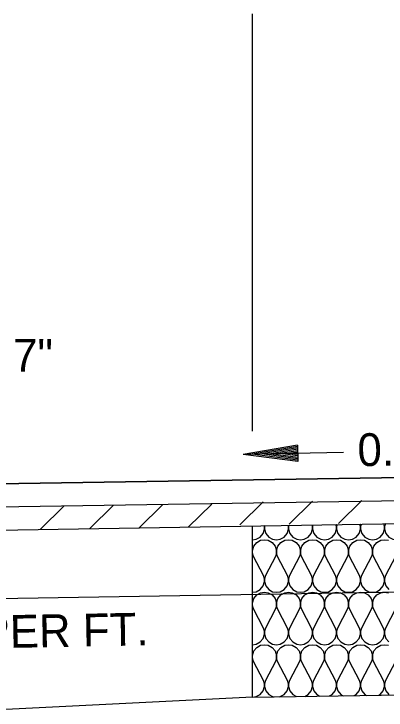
# Model space of a CAD drawing. Extents: x 635488 to 635865, y 290537 to 290973.
# Drawn here: x 635687.68 to 635694.5, y 290665.33 to 290678.07 of the extents above; entities that cross this region are included whole.
import ezdxf

# ---------------------------------------------------------------- set-up
doc = ezdxf.new("R2010")
doc.units = 0
for name, color, linetype in [('Default', 7, 'Continuous'), ('E_Existing ROW', 7, 'Continuous'), ('Level 13', 7, 'Continuous'), ('Level 3', 7, 'Continuous'), ('Level 43', 7, 'Continuous'), ('R_Dimension', 7, 'Continuous')]:
    doc.layers.add(name, color=color, linetype=linetype)

msp = doc.modelspace()

# ---------------------------------------------------------------- linework, layer by layer
at = {"layer": 'Default'}
for points in [[(635692.051, 290665.568), (635705.801, 290665.784), (635719.551, 290665.568)], [(635692.051, 290665.568), (635686.062, 290665.27)]]:
    msp.add_lwpolyline(points, dxfattribs=at)
at = {"layer": 'E_Existing ROW'}
for points in [[(635692.051, 290668.448), (635692.121, 290668.458), (635692.191, 290668.498), (635692.246, 290668.563), (635692.271, 290668.643), (635692.271, 290668.693), (635692.267, 290668.706)], [(635692.275, 290668.706), (635692.271, 290668.693), (635692.271, 290668.643), (635692.296, 290668.563), (635692.351, 290668.498), (635692.421, 290668.458), (635692.491, 290668.448)], [(635692.491, 290668.448), (635692.561, 290668.458), (635692.631, 290668.498), (635692.686, 290668.563), (635692.711, 290668.643), (635692.711, 290668.693), (635692.705, 290668.713)], [(635692.717, 290668.714), (635692.711, 290668.693), (635692.711, 290668.643), (635692.736, 290668.563), (635692.791, 290668.498), (635692.861, 290668.458), (635692.931, 290668.448)], [(635692.931, 290668.448), (635693.001, 290668.458), (635693.071, 290668.498), (635693.126, 290668.563), (635693.151, 290668.643), (635693.151, 290668.693), (635693.143, 290668.721)], [(635693.159, 290668.721), (635693.151, 290668.693), (635693.151, 290668.643), (635693.176, 290668.563), (635693.231, 290668.498), (635693.301, 290668.458), (635693.371, 290668.448)], [(635693.371, 290668.448), (635693.441, 290668.458), (635693.511, 290668.498), (635693.566, 290668.563), (635693.591, 290668.643), (635693.591, 290668.693), (635693.581, 290668.728)], [(635693.601, 290668.728), (635693.591, 290668.693), (635693.591, 290668.643), (635693.616, 290668.563), (635693.671, 290668.498), (635693.741, 290668.458), (635693.811, 290668.448)], [(635693.811, 290668.448), (635693.881, 290668.458), (635693.951, 290668.498), (635694.006, 290668.563), (635694.031, 290668.643), (635694.031, 290668.693), (635694.019, 290668.735)], [(635694.043, 290668.735), (635694.031, 290668.693), (635694.031, 290668.643), (635694.056, 290668.563), (635694.111, 290668.498), (635694.181, 290668.458), (635694.251, 290668.448)], [(635694.251, 290668.448), (635694.321, 290668.458), (635694.391, 290668.498), (635694.446, 290668.563), (635694.471, 290668.643), (635694.471, 290668.693), (635694.457, 290668.742)], [(635694.485, 290668.743), (635694.471, 290668.693), (635694.471, 290668.643), (635694.496, 290668.563), (635694.551, 290668.498), (635694.621, 290668.458), (635694.691, 290668.448)], [(635692.051, 290667.488), (635692.121, 290667.498), (635692.191, 290667.538), (635692.246, 290667.603), (635692.271, 290667.683), (635692.271, 290667.733), (635692.254, 290667.792), (635692.068, 290668.143), (635692.051, 290668.203), (635692.051, 290668.253), (635692.076, 290668.333), (635692.131, 290668.398), (635692.201, 290668.438), (635692.271, 290668.448), (635692.341, 290668.438), (635692.411, 290668.398), (635692.466, 290668.333), (635692.491, 290668.253), (635692.491, 290668.203), (635692.474, 290668.143), (635692.288, 290667.792), (635692.271, 290667.733), (635692.271, 290667.683), (635692.296, 290667.603), (635692.351, 290667.538), (635692.421, 290667.498), (635692.491, 290667.488)], [(635692.491, 290667.488), (635692.561, 290667.498), (635692.631, 290667.538), (635692.686, 290667.603), (635692.711, 290667.683), (635692.711, 290667.733), (635692.694, 290667.792), (635692.508, 290668.143), (635692.491, 290668.203), (635692.491, 290668.253), (635692.516, 290668.333), (635692.571, 290668.398), (635692.641, 290668.438), (635692.711, 290668.448), (635692.781, 290668.438), (635692.851, 290668.398), (635692.906, 290668.333), (635692.931, 290668.253), (635692.931, 290668.203), (635692.914, 290668.143), (635692.728, 290667.792), (635692.711, 290667.733), (635692.711, 290667.683), (635692.736, 290667.603), (635692.791, 290667.538), (635692.861, 290667.498), (635692.931, 290667.488)], [(635692.931, 290667.488), (635693.001, 290667.498), (635693.071, 290667.538), (635693.126, 290667.603), (635693.151, 290667.683), (635693.151, 290667.733), (635693.134, 290667.792), (635692.948, 290668.143), (635692.931, 290668.203), (635692.931, 290668.253), (635692.956, 290668.333), (635693.011, 290668.398), (635693.081, 290668.438), (635693.151, 290668.448), (635693.221, 290668.438), (635693.291, 290668.398), (635693.346, 290668.333), (635693.371, 290668.253), (635693.371, 290668.203), (635693.354, 290668.143), (635693.168, 290667.792), (635693.151, 290667.733), (635693.151, 290667.683), (635693.176, 290667.603), (635693.231, 290667.538), (635693.301, 290667.498), (635693.371, 290667.488)], [(635693.371, 290667.488), (635693.441, 290667.498), (635693.511, 290667.538), (635693.566, 290667.603), (635693.591, 290667.683), (635693.591, 290667.733), (635693.574, 290667.792), (635693.388, 290668.143), (635693.371, 290668.203), (635693.371, 290668.253), (635693.396, 290668.333), (635693.451, 290668.398), (635693.521, 290668.438), (635693.591, 290668.448), (635693.661, 290668.438), (635693.731, 290668.398), (635693.786, 290668.333), (635693.811, 290668.253), (635693.811, 290668.203), (635693.794, 290668.143), (635693.608, 290667.792), (635693.591, 290667.733), (635693.591, 290667.683), (635693.616, 290667.603), (635693.671, 290667.538), (635693.741, 290667.498), (635693.811, 290667.488)], [(635693.811, 290667.488), (635693.881, 290667.498), (635693.951, 290667.538), (635694.006, 290667.603), (635694.031, 290667.683), (635694.031, 290667.733), (635694.014, 290667.792), (635693.828, 290668.143), (635693.811, 290668.203), (635693.811, 290668.253), (635693.836, 290668.333), (635693.891, 290668.398), (635693.961, 290668.438), (635694.031, 290668.448), (635694.101, 290668.438), (635694.171, 290668.398), (635694.226, 290668.333), (635694.251, 290668.253), (635694.251, 290668.203), (635694.234, 290668.143), (635694.048, 290667.792), (635694.031, 290667.733), (635694.031, 290667.683), (635694.056, 290667.603), (635694.111, 290667.538), (635694.181, 290667.498), (635694.251, 290667.488)], [(635694.251, 290667.488), (635694.321, 290667.498), (635694.391, 290667.538), (635694.446, 290667.603), (635694.471, 290667.683), (635694.471, 290667.733), (635694.454, 290667.792), (635694.268, 290668.143), (635694.251, 290668.203), (635694.251, 290668.253), (635694.276, 290668.333), (635694.331, 290668.398), (635694.401, 290668.438), (635694.471, 290668.448), (635694.541, 290668.438)], [(635694.674, 290668.143), (635694.488, 290667.792), (635694.471, 290667.733), (635694.471, 290667.683), (635694.496, 290667.603), (635694.551, 290667.538)], [(635692.051, 290666.528), (635692.121, 290666.538), (635692.191, 290666.578), (635692.246, 290666.643), (635692.271, 290666.723), (635692.271, 290666.773), (635692.254, 290666.832), (635692.068, 290667.183), (635692.051, 290667.243), (635692.051, 290667.293), (635692.076, 290667.373), (635692.131, 290667.438), (635692.201, 290667.478), (635692.271, 290667.488), (635692.341, 290667.478), (635692.411, 290667.438), (635692.466, 290667.373), (635692.491, 290667.293), (635692.491, 290667.243), (635692.474, 290667.183), (635692.288, 290666.832), (635692.271, 290666.773), (635692.271, 290666.723), (635692.296, 290666.643), (635692.351, 290666.578), (635692.421, 290666.538), (635692.491, 290666.528)], [(635692.491, 290666.528), (635692.561, 290666.538), (635692.631, 290666.578), (635692.686, 290666.643), (635692.711, 290666.723), (635692.711, 290666.773), (635692.694, 290666.832), (635692.508, 290667.183), (635692.491, 290667.243), (635692.491, 290667.293), (635692.516, 290667.373), (635692.571, 290667.438), (635692.641, 290667.478), (635692.711, 290667.488), (635692.781, 290667.478), (635692.851, 290667.438), (635692.906, 290667.373), (635692.931, 290667.293), (635692.931, 290667.243), (635692.914, 290667.183), (635692.728, 290666.832), (635692.711, 290666.773), (635692.711, 290666.723), (635692.736, 290666.643), (635692.791, 290666.578), (635692.861, 290666.538), (635692.931, 290666.528)], [(635692.931, 290666.528), (635693.001, 290666.538), (635693.071, 290666.578), (635693.126, 290666.643), (635693.151, 290666.723), (635693.151, 290666.773), (635693.134, 290666.832), (635692.948, 290667.183), (635692.931, 290667.243), (635692.931, 290667.293), (635692.956, 290667.373), (635693.011, 290667.438), (635693.081, 290667.478), (635693.151, 290667.488), (635693.221, 290667.478), (635693.291, 290667.438), (635693.346, 290667.373), (635693.371, 290667.293), (635693.371, 290667.243), (635693.354, 290667.183), (635693.168, 290666.832), (635693.151, 290666.773), (635693.151, 290666.723), (635693.176, 290666.643), (635693.231, 290666.578), (635693.301, 290666.538), (635693.371, 290666.528)], [(635693.371, 290666.528), (635693.441, 290666.538), (635693.511, 290666.578), (635693.566, 290666.643), (635693.591, 290666.723), (635693.591, 290666.773), (635693.574, 290666.832), (635693.388, 290667.183), (635693.371, 290667.243), (635693.371, 290667.293), (635693.396, 290667.373), (635693.451, 290667.438), (635693.521, 290667.478), (635693.591, 290667.488), (635693.661, 290667.478), (635693.731, 290667.438), (635693.786, 290667.373), (635693.811, 290667.293), (635693.811, 290667.243), (635693.794, 290667.183), (635693.608, 290666.832), (635693.591, 290666.773), (635693.591, 290666.723), (635693.616, 290666.643), (635693.671, 290666.578), (635693.741, 290666.538), (635693.811, 290666.528)], [(635693.811, 290666.528), (635693.881, 290666.538), (635693.951, 290666.578), (635694.006, 290666.643), (635694.031, 290666.723), (635694.031, 290666.773), (635694.014, 290666.832), (635693.828, 290667.183), (635693.811, 290667.243), (635693.811, 290667.293), (635693.836, 290667.373), (635693.891, 290667.438), (635693.961, 290667.478), (635694.031, 290667.488), (635694.101, 290667.478), (635694.171, 290667.438), (635694.226, 290667.373), (635694.251, 290667.293), (635694.251, 290667.243), (635694.234, 290667.183), (635694.048, 290666.832), (635694.031, 290666.773), (635694.031, 290666.723), (635694.056, 290666.643), (635694.111, 290666.578), (635694.181, 290666.538), (635694.251, 290666.528)], [(635694.251, 290666.528), (635694.321, 290666.538), (635694.391, 290666.578), (635694.446, 290666.643), (635694.471, 290666.723), (635694.471, 290666.773), (635694.454, 290666.832), (635694.268, 290667.183), (635694.251, 290667.243), (635694.251, 290667.293), (635694.276, 290667.373), (635694.331, 290667.438), (635694.401, 290667.478), (635694.471, 290667.488), (635694.541, 290667.478)], [(635694.674, 290667.183), (635694.488, 290666.832), (635694.471, 290666.773), (635694.471, 290666.723), (635694.496, 290666.643), (635694.551, 290666.578)], [(635692.051, 290665.568), (635692.121, 290665.578), (635692.191, 290665.618), (635692.246, 290665.683), (635692.271, 290665.763), (635692.271, 290665.813), (635692.254, 290665.872), (635692.068, 290666.223), (635692.051, 290666.283), (635692.051, 290666.333), (635692.076, 290666.413), (635692.131, 290666.478), (635692.201, 290666.518), (635692.271, 290666.528), (635692.341, 290666.518), (635692.411, 290666.478), (635692.466, 290666.413), (635692.491, 290666.333), (635692.491, 290666.283), (635692.474, 290666.223), (635692.288, 290665.872), (635692.271, 290665.813), (635692.271, 290665.763), (635692.296, 290665.683), (635692.351, 290665.618), (635692.421, 290665.578), (635692.447, 290665.574)], [(635692.545, 290665.575), (635692.561, 290665.578), (635692.631, 290665.618), (635692.686, 290665.683), (635692.711, 290665.763), (635692.711, 290665.813), (635692.694, 290665.872), (635692.508, 290666.223), (635692.491, 290666.283), (635692.491, 290666.333), (635692.516, 290666.413), (635692.571, 290666.478), (635692.641, 290666.518), (635692.711, 290666.528), (635692.781, 290666.518), (635692.851, 290666.478), (635692.906, 290666.413), (635692.931, 290666.333), (635692.931, 290666.283), (635692.914, 290666.223), (635692.728, 290665.872), (635692.711, 290665.813), (635692.711, 290665.763), (635692.736, 290665.683), (635692.791, 290665.618), (635692.856, 290665.58)], [(635693.01, 290665.583), (635693.071, 290665.618), (635693.126, 290665.683), (635693.151, 290665.763), (635693.151, 290665.813), (635693.134, 290665.872), (635692.948, 290666.223), (635692.931, 290666.283), (635692.931, 290666.333), (635692.956, 290666.413), (635693.011, 290666.478), (635693.081, 290666.518), (635693.151, 290666.528), (635693.221, 290666.518), (635693.291, 290666.478), (635693.346, 290666.413), (635693.371, 290666.333), (635693.371, 290666.283), (635693.354, 290666.223), (635693.168, 290665.872), (635693.151, 290665.813), (635693.151, 290665.763), (635693.176, 290665.683), (635693.231, 290665.618), (635693.284, 290665.587)], [(635693.462, 290665.59), (635693.511, 290665.618), (635693.566, 290665.683), (635693.591, 290665.763), (635693.591, 290665.813), (635693.574, 290665.872), (635693.388, 290666.223), (635693.371, 290666.283), (635693.371, 290666.333), (635693.396, 290666.413), (635693.451, 290666.478), (635693.521, 290666.518), (635693.591, 290666.528), (635693.661, 290666.518), (635693.731, 290666.478), (635693.786, 290666.413), (635693.811, 290666.333), (635693.811, 290666.283), (635693.794, 290666.223), (635693.608, 290665.872), (635693.591, 290665.813), (635693.591, 290665.763), (635693.616, 290665.683), (635693.671, 290665.618), (635693.713, 290665.594)], [(635693.915, 290665.597), (635693.951, 290665.618), (635694.006, 290665.683), (635694.031, 290665.763), (635694.031, 290665.813), (635694.014, 290665.872), (635693.828, 290666.223), (635693.811, 290666.283), (635693.811, 290666.333), (635693.836, 290666.413), (635693.891, 290666.478), (635693.961, 290666.518), (635694.031, 290666.528), (635694.101, 290666.518), (635694.171, 290666.478), (635694.226, 290666.413), (635694.251, 290666.333), (635694.251, 290666.283), (635694.234, 290666.223), (635694.048, 290665.872), (635694.031, 290665.813), (635694.031, 290665.763), (635694.056, 290665.683), (635694.111, 290665.618), (635694.141, 290665.6)], [(635694.367, 290665.604), (635694.391, 290665.618), (635694.446, 290665.683), (635694.471, 290665.763), (635694.471, 290665.813), (635694.454, 290665.872), (635694.268, 290666.223), (635694.251, 290666.283), (635694.251, 290666.333), (635694.276, 290666.413), (635694.331, 290666.478), (635694.401, 290666.518), (635694.471, 290666.528), (635694.541, 290666.518)], [(635694.674, 290666.223), (635694.488, 290665.872), (635694.471, 290665.813), (635694.471, 290665.763), (635694.496, 290665.683), (635694.551, 290665.618)]]:
    msp.add_lwpolyline(points, dxfattribs=at)
at = {"layer": 'Level 3'}
for p, q in [((635684.551, 290669.425), (635702.051, 290669.7)), ((635702.051, 290669.7), (635684.551, 290669.425)), ((635684.551, 290669.008), (635702.051, 290669.283)), ((635684.551, 290669.008), (635702.051, 290669.283)), ((635693.625, 290668.745), (635694.052, 290669.168)), ((635688.17, 290668.641), (635688.598, 290669.064)), ((635689.072, 290668.654), (635689.5, 290669.077)), ((635689.974, 290668.667), (635690.402, 290669.089)), ((635690.876, 290668.68), (635691.304, 290669.102)), ((635691.821, 290668.72), (635692.248, 290669.142)), ((635692.723, 290668.732), (635693.15, 290669.155)), ((635681.426, 290668.529), (635702.051, 290668.866)), ((635681.426, 290667.279), (635702.051, 290667.616))]:
    msp.add_line(p, q, dxfattribs=at)
msp.add_lwpolyline([(635692.051, 290665.568), (635692.051, 290668.703)], dxfattribs=at)
at = {"layer": 'Level 43'}
for p, q in [((635692.051, 290670.433), (635692.051, 290678.07)), ((635693.716, 290670.045), (635691.881, 290670.011))]:
    msp.add_line(p, q, dxfattribs=at)
at = {"layer": 'R_Dimension'}
for p, q in [((635692.878, 290670.18), (635691.881, 290670.011)), ((635692.878, 290670.18), (635692.884, 290669.88)), ((635692.879, 290670.155), (635692.048, 290670.014)), ((635692.879, 290670.129), (635692.22, 290670.018)), ((635692.88, 290670.104), (635692.387, 290670.021)), ((635692.88, 290670.078), (635692.556, 290670.024)), ((635692.88, 290670.053), (635692.723, 290670.027)), ((635692.884, 290669.88), (635691.881, 290670.011)), ((635692.883, 290669.905), (635692.048, 290670.014)), ((635692.883, 290669.93), (635692.22, 290670.018)), ((635692.882, 290669.955), (635692.387, 290670.021)), ((635692.882, 290669.981), (635692.556, 290670.024)), ((635692.881, 290670.006), (635692.723, 290670.027))]:
    msp.add_line(p, q, dxfattribs=at)

# ---------------------------------------------------------------- texts
at = {"layer": 'Level 13'}
for height, p in [(0.6, (635693.98, 290669.793)), (0.59999, (635683.866, 290666.4))]:
    msp.add_text('0.02 FT. PER FT.', height=height, rotation=1.0577, dxfattribs=at).set_placement(p)
at = {"layer": 'Level 3'}
msp.add_text('7"', height=0.6, dxfattribs=at).set_placement((635687.666, 290671.523))

doc.saveas('drawing.dxf')
